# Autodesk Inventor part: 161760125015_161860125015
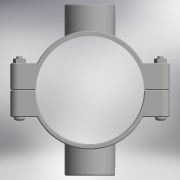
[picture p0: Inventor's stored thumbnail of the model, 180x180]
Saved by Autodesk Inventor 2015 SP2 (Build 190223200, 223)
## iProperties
Created: 2017-05
Part Number: 161760125015_161860125015
Material: Generic
Description: PLASSON DOUBLE SADDLE 125-1.1/2"
Document SubType Name: Modeling
Designer: KIM
Density: 1 g/cm^3
Appearance: Default
Author: KIM
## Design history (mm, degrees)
derived "16176.ipt"
feature "Solid1::16176.ipt"
feature "Solid2::16176.ipt"
tag "TaggingFeature1"
body "Solid1"
body "Solid2"
other parameters: "d0" = 137.5, "d1" = 184, "d2" = 62.5, "d3" = 125, "d4" = 124, "d5" = 0, "d6" = 9.2, "d7" = 184, "d8" = 0.1, "d10" = 0, "d11" = 1.25, "d20" = 1.25, "d23" = 1.25, "d36" = 13, "d37" = 10.4, "d38" = 70.5, "d39" = 0, "d40" = 3, "d41" = 5, "d42" = 0, "d43" = 8, "d44" = 3, "d45" = 0, "d46" = 1.25, "d52" = 44.845, "d53" = 25, "d54" = 0, "d57" = 0, "d58" = 135, "d60" = 0, "d62" = 13, "d63" = 10.4, "d66" = 103.2, "d67" = 198, "d68" = 58.2985, "d69" = 44.845, "d70" = 25, "d71" = 0, "d74" = 0, "d75" = 1.25, "d_" = 125, "G_" = 44.845, "A_" = 99, "L_" = 184, "L_1" = 124, "l_2" = 25
